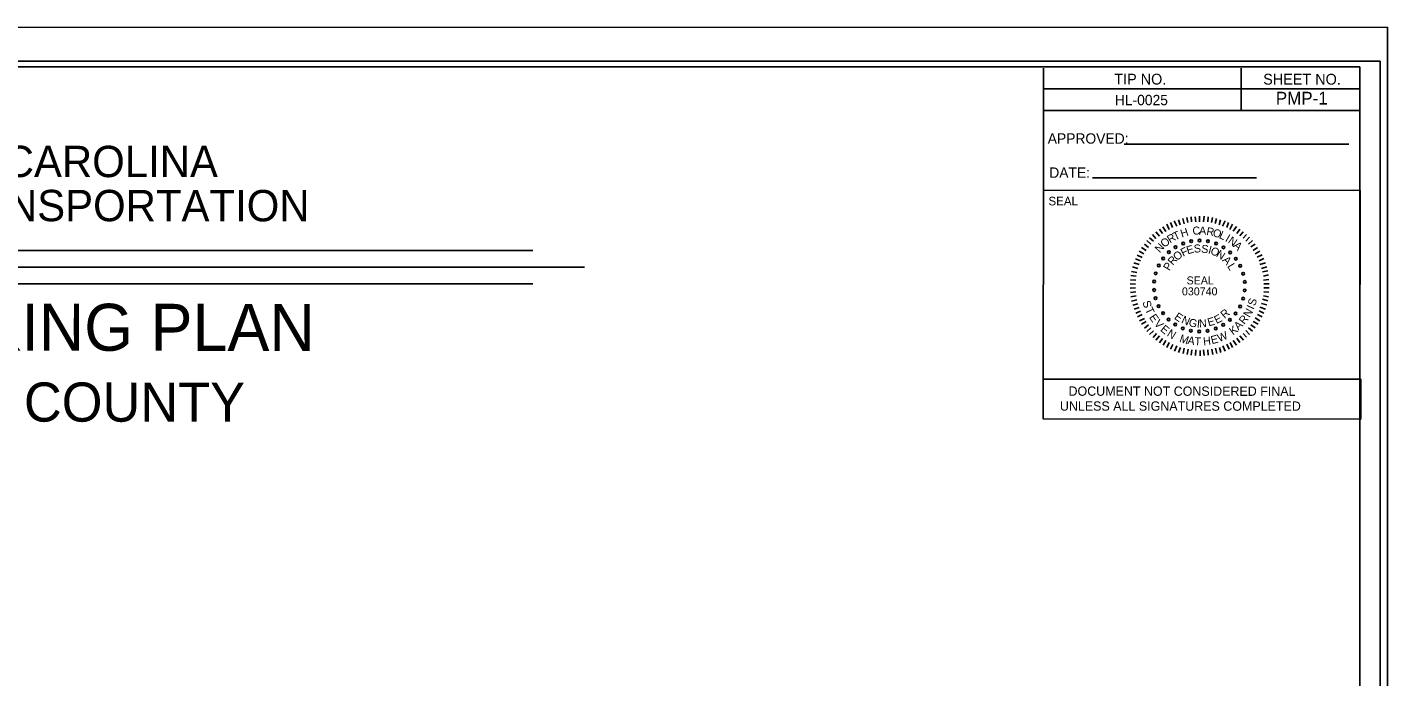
# Model space of a CAD drawing. Extents: x 2088685 to 2091711, y 751320 to 752417.
# Drawn here: x 2090071 to 2090874, y 752034 to 752417 of the extents above; entities that cross this region are included whole.
import ezdxf

# ---------------------------------------------------------------- set-up
doc = ezdxf.new("R2010")
doc.units = 0
for name, color, linetype in [('Default', 7, 'Continuous'), ('Matchline Text', 7, 'Continuous'), ('Old_Level_9', 7, 'Continuous'), ('Sheet Block Title CELL', 7, 'Continuous'), ('Sheet Data Field CELL', 7, 'Continuous'), ('Sheet Plan CELL', 7, 'Continuous'), ('Sheet Plot Border Inside CELL', 7, 'Continuous'), ('Sheet Plot Border Outside CELL', 7, 'Continuous'), ('Sheet Sticker Exception Certification CELL', 7, 'Continuous'), ('Sheet Title CELL', 7, 'Continuous')]:
    doc.layers.add(name, color=color, linetype=linetype)

msp = doc.modelspace()

# ---------------------------------------------------------------- linework, layer by layer
at = {"layer": 'Default'}
msp.add_line((2090718.89, 752347.92), (2090851.47, 752347.86), dxfattribs=at)
at = {"layer": 'Matchline Text'}
for p, q in [((2090787.95, 752367.8), (2090787.96, 752392.75)), ((2090858.18, 752392.71), (2090858.18, 752392.71)), ((2090858.18, 752392.71), (2090858.18, 752392.71)), ((2090858.18, 752392.71), (2090858.18, 752392.71)), ((2090858.18, 752392.71), (2090858.18, 752392.71)), ((2090858.18, 752392.71), (2090858.18, 752392.71)), ((2090858.18, 752392.71), (2090858.18, 752392.71)), ((2090858.18, 752392.71), (2090858.18, 752392.71)), ((2090858.18, 752392.71), (2090858.18, 752392.71)), ((2090700.2, 752328.03), (2090796.96, 752327.98))]:
    msp.add_line(p, q, dxfattribs=at)
at = {"layer": 'Old_Level_9'}
for p, q in [((2090748.44, 752302.61), (2090749.94, 752299.61)), ((2090751.06, 752303.36), (2090751.94, 752300.36)), ((2090753.44, 752304.11), (2090754.31, 752300.99)), ((2090755.81, 752304.61), (2090756.44, 752301.61)), ((2090758.44, 752304.99), (2090758.69, 752301.99)), ((2090760.81, 752305.11), (2090761.19, 752302.11)), ((2090763.44, 752305.36), (2090763.44, 752302.11)), ((2090766.06, 752305.36), (2090765.69, 752302.11)), ((2090768.44, 752304.99), (2090768.19, 752301.99)), ((2090771.06, 752304.61), (2090770.44, 752301.61)), ((2090773.44, 752304.11), (2090772.56, 752301.11)), ((2090775.81, 752303.36), (2090774.94, 752300.36)), ((2090778.44, 752302.61), (2090776.94, 752299.61)), ((2090735.69, 752294.61), (2090737.69, 752292.24)), ((2090737.69, 752296.24), (2090739.69, 752293.61)), ((2090739.69, 752297.74), (2090741.56, 752295.24)), ((2090741.69, 752299.11), (2090743.56, 752296.36)), ((2090744.06, 752300.61), (2090745.56, 752297.61)), ((2090746.31, 752301.61), (2090747.44, 752298.74)), ((2090780.56, 752301.61), (2090779.44, 752298.74)), ((2090782.81, 752300.61), (2090781.31, 752297.61)), ((2090785.19, 752299.36), (2090783.31, 752296.61)), ((2090787.19, 752297.74), (2090785.31, 752295.24)), ((2090789.19, 752296.24), (2090787.19, 752293.74)), ((2090791.19, 752294.61), (2090789.19, 752292.36)), ((2090729.19, 752286.86), (2090731.94, 752285.24)), ((2090730.81, 752288.99), (2090733.19, 752286.99)), ((2090732.19, 752290.99), (2090734.56, 752288.86)), ((2090733.94, 752292.74), (2090736.19, 752290.61)), ((2090792.94, 752292.99), (2090790.69, 752290.61)), ((2090794.69, 752290.99), (2090792.31, 752288.99)), ((2090796.31, 752288.99), (2090793.69, 752287.24)), ((2090797.69, 752286.99), (2090795.06, 752285.24)), ((2090725.56, 752280.24), (2090728.56, 752278.99)), ((2090726.56, 752282.49), (2090729.56, 752280.99)), ((2090727.81, 752284.86), (2090730.56, 752283.24)), ((2090799.06, 752284.86), (2090796.31, 752283.24)), ((2090800.31, 752282.61), (2090797.31, 752281.24)), ((2090801.31, 752280.49), (2090798.56, 752278.99)), ((2090722.81, 752270.49), (2090725.94, 752270.11)), ((2090723.19, 752272.86), (2090726.31, 752272.24)), ((2090723.81, 752275.49), (2090726.94, 752274.61)), ((2090724.56, 752277.86), (2090727.81, 752276.86)), ((2090802.31, 752277.86), (2090799.06, 752276.86)), ((2090803.06, 752275.49), (2090799.94, 752274.61)), ((2090803.69, 752273.11), (2090800.56, 752272.49)), ((2090804.06, 752270.74), (2090801.06, 752270.11)), ((2090722.44, 752265.49), (2090725.56, 752265.24)), ((2090722.44, 752262.86), (2090725.56, 752263.11)), ((2090722.56, 752267.86), (2090725.81, 752267.74)), ((2090804.31, 752268.11), (2090801.06, 752267.74)), ((2090804.44, 752265.49), (2090801.31, 752265.49)), ((2090804.44, 752263.11), (2090801.31, 752263.11)), ((2090722.56, 752260.36), (2090725.81, 752260.74)), ((2090722.81, 752257.86), (2090725.94, 752258.36)), ((2090723.19, 752255.36), (2090726.31, 752256.11)), ((2090803.69, 752255.49), (2090800.56, 752256.36)), ((2090804.06, 752257.86), (2090801.06, 752258.49)), ((2090804.31, 752260.49), (2090801.31, 752260.74)), ((2090723.94, 752252.99), (2090726.94, 752253.74)), ((2090724.81, 752250.61), (2090727.81, 752251.49)), ((2090725.81, 752248.11), (2090728.56, 752249.36)), ((2090726.81, 752245.99), (2090729.56, 752247.36)), ((2090800.31, 752245.99), (2090797.56, 752247.36)), ((2090801.31, 752248.11), (2090798.56, 752249.61)), ((2090802.31, 752250.61), (2090799.06, 752251.74)), ((2090803.06, 752253.11), (2090799.94, 752253.99)), ((2090727.94, 752243.61), (2090730.81, 752245.11)), ((2090729.19, 752241.61), (2090731.94, 752243.24)), ((2090730.81, 752239.36), (2090733.31, 752241.36)), ((2090732.31, 752237.36), (2090734.69, 752239.61)), ((2090794.69, 752237.61), (2090792.31, 752239.61)), ((2090796.31, 752239.61), (2090793.69, 752241.36)), ((2090797.94, 752241.61), (2090795.06, 752243.36)), ((2090799.06, 752243.61), (2090796.31, 752245.36)), ((2090733.94, 752235.61), (2090736.31, 752237.74)), ((2090735.94, 752233.86), (2090737.94, 752236.24)), ((2090737.69, 752232.24), (2090739.69, 752234.86)), ((2090739.69, 752230.61), (2090741.56, 752233.24)), ((2090741.94, 752229.24), (2090743.56, 752231.99)), ((2090744.06, 752227.99), (2090745.56, 752230.86)), ((2090782.94, 752227.99), (2090781.56, 752230.86)), ((2090785.19, 752229.24), (2090783.31, 752231.99)), ((2090787.19, 752230.86), (2090785.31, 752233.36)), ((2090789.31, 752232.24), (2090787.19, 752234.86)), ((2090791.19, 752233.99), (2090789.19, 752236.24)), ((2090792.94, 752235.61), (2090790.69, 752237.99)), ((2090746.31, 752226.86), (2090747.69, 752229.61)), ((2090748.69, 752225.86), (2090749.94, 752228.86)), ((2090751.06, 752224.99), (2090752.06, 752227.99)), ((2090753.69, 752224.49), (2090754.31, 752227.49)), ((2090756.06, 752223.86), (2090756.69, 752226.99)), ((2090758.44, 752223.49), (2090758.81, 752226.49)), ((2090761.06, 752223.24), (2090761.19, 752226.49)), ((2090763.69, 752223.11), (2090763.69, 752226.24)), ((2090766.06, 752223.24), (2090765.81, 752226.49)), ((2090768.56, 752223.49), (2090768.19, 752226.49)), ((2090771.19, 752223.86), (2090770.56, 752226.99)), ((2090773.56, 752224.49), (2090772.81, 752227.49)), ((2090775.94, 752224.99), (2090775.19, 752227.99)), ((2090778.44, 752225.86), (2090777.19, 752228.99)), ((2090780.81, 752226.86), (2090779.44, 752229.86))]:
    msp.add_line(p, q, dxfattribs=at)
for centre in [(2090749.27, 752287.13), (2090753.72, 752289.32), (2090758.49, 752290.66), (2090763.43, 752291.1), (2090768.37, 752290.62), (2090773.13, 752289.24), (2090777.56, 752287.02), (2090741.95, 752280.51), (2090745.31, 752284.16), (2090781.5, 752284.02), (2090784.83, 752280.34), (2090737.52, 752271.69), (2090739.33, 752276.3), (2090787.42, 752276.11), (2090789.19, 752271.49), (2090736.57, 752261.86), (2090736.59, 752266.82), (2090790.06, 752261.65), (2090790.08, 752266.61), (2090737.46, 752256.99), (2090789.13, 752256.78), (2090739.24, 752252.36), (2090741.83, 752248.13), (2090784.7, 752247.97), (2090787.32, 752252.17), (2090745.15, 752244.46), (2090749.1, 752241.45), (2090753.53, 752239.23), (2090758.29, 752237.85), (2090763.22, 752237.38), (2090768.16, 752237.81), (2090772.93, 752239.15), (2090777.38, 752241.34), (2090781.35, 752244.32)]:
    msp.add_circle(centre, 0.788, dxfattribs=at)
at = {"layer": 'Sheet Block Title CELL'}
for p, q in [((2090671.22, 752367.86), (2090671.23, 752392.8)), ((2090787.95, 752367.8), (2090787.96, 752392.75)), ((2090671.23, 752380.59), (2090787.95, 752380.53)), ((2090787.95, 752380.53), (2090858.17, 752380.49)), ((2090671.2, 752320.69), (2090671.22, 752367.86)), ((2090671.22, 752367.86), (2090858.17, 752367.76))]:
    msp.add_line(p, q, dxfattribs=at)
for points in [[(2090858, 752393.6), (2089358.33, 752393.49), (2089358.41, 751343.72), (2090858.08, 751343.83)], [(2090671.2, 752320.69), (2090858.14, 752320.6), (2090858.09, 752209.23), (2090671.15, 752209.31)]]:
    msp.add_lwpolyline(points, close=True, dxfattribs=at)
at = {"layer": 'Sheet Plan CELL'}
for p, q in [((2090874.42, 752416.91), (2090874.42, 752416.91)), ((2090869.93, 752396.91), (2090869.93, 752396.91))]:
    msp.add_line(p, q, dxfattribs=at)
at = {"layer": 'Sheet Plot Border Inside CELL'}
msp.add_lwpolyline([(2090869.93, 752396.91), (2089204.86, 752396.79), (2089204.94, 751341.13), (2090870.01, 751341.25)], close=True, dxfattribs=at)
at = {"layer": 'Sheet Plot Border Outside CELL'}
msp.add_lwpolyline([(2090874.42, 752416.91), (2089191.88, 752416.79), (2089191.96, 751321.13), (2090874.5, 751321.25)], close=True, dxfattribs=at)
at = {"layer": 'Sheet Sticker Exception Certification CELL'}
msp.add_lwpolyline([(2090671.15, 752209.31), (2090858.55, 752209.23), (2090858.54, 752185.73), (2090671.14, 752185.82)], close=True, dxfattribs=at)
at = {"layer": 'Sheet Title CELL'}
for p, q in [((2089677.86, 752285.08), (2090369.97, 752285.08)), ((2089645.9, 752275.34), (2090400.31, 752275.34)), ((2089677.86, 752265.58), (2090369.97, 752265.58))]:
    msp.add_line(p, q, dxfattribs=at)

# ---------------------------------------------------------------- texts
at = {"layer": 'Default'}
for s, height, p in [('TIP NO.', 6.356, (2090713.08, 752383.12)), ('SHEET NO.', 6.356, (2090800.97, 752383.07)), ('HL-0025', 6.108, (2090713.41, 752370.9)), ('APPROVED:', 6.108, (2090673.8, 752348.21)), ('DATE:', 6.108, (2090674.71, 752328.07)), ('SEAL', 5.093, (2090674.22, 752311.78))]:
    msp.add_text(s, height=height, rotation=359.96835, dxfattribs=at).set_placement(p)
at = {"layer": 'Old_Level_9'}
for s, height, rotation, p in [('R', 4.72, 32.17545, (2090746.06, 752289.24)), ('T', 4.72, 25.43578, (2090749.06, 752290.99)), ('H', 4.72, 17.74335, (2090752.94, 752292.74)), ('C', 4.72, 4.93991, (2090759.44, 752294.36)), ('A', 4.72, 357.97486, (2090763.06, 752294.61)), ('R', 4.72, 350.02156, (2090767.19, 752294.36)), ('O', 4.72, 343.0868, (2090770.81, 752293.74)), ('L', 4.72, 335.7459, (2090774.56, 752292.61)), ('I', 4.72, 330.80596, (2090778.19, 752290.86)), ('N', 4.72, 48.06666, (2090739.94, 752283.49)), ('O', 4.72, 39.94421, (2090742.69, 752286.61)), ('F', 4.7, 26.39995, (2090753.69, 752281.49)), ('E', 4.7, 16.58893, (2090756.44, 752282.86)), ('S', 4.7, 4.46802, (2090760.19, 752283.86)), ('S', 4.7, 353.04145, (2090764.19, 752283.99)), ('I', 4.7, 345.48207, (2090768.19, 752283.49)), ('O', 4.7, 337.87488, (2090769.44, 752283.24)), ('N', 4.72, 324.90384, (2090779.81, 752289.99)), ('A', 4.72, 317.00507, (2090782.94, 752287.61)), ('R', 4.7, 49.7478, (2090747.69, 752276.11)), ('O', 4.7, 38.25181, (2090750.06, 752278.86)), ('N', 4.7, 327.39302, (2090772.81, 752281.86)), ('A', 4.7, 313.94377, (2090776.56, 752279.24)), ('P', 4.7, 60.12364, (2090745.69, 752272.86)), ('L', 4.7, 301.53231, (2090779.56, 752275.86)), ('S', 4.72, 288.212, (2090729.62, 752254.76)), ('S', 4.72, 72.25788, (2090796.16, 752252.12)), ('T', 4.72, 295.62438, (2090731.11, 752250.36)), ('E', 4.72, 303.82249, (2090733.45, 752245.76)), ('E', 4.7, 324.86919, (2090748.06, 752245.11)), ('N', 4.7, 336.05836, (2090752.31, 752242.61)), ('E', 4.7, 27.15681, (2090773.44, 752241.74)), ('R', 4.7, 40.34926, (2090778.19, 752244.74)), ('R', 4.72, 51.15031, (2090789.8, 752241.21)), ('N', 4.72, 59.37257, (2090792.87, 752245.26)), ('I', 4.72, 66.04639, (2090795.29, 752250.01)), ('V', 4.72, 311.92979, (2090736.27, 752241.79)), ('E', 4.72, 320.23124, (2090739.89, 752238.07)), ('N', 4.72, 328.32899, (2090743.8, 752235.04)), ('G', 4.7, 347.48124, (2090756.69, 752240.61)), ('I', 4.7, 355.62459, (2090761.69, 752239.74)), ('N', 4.7, 3.12779, (2090763.19, 752239.74)), ('E', 4.7, 15.80569, (2090768.81, 752240.36)), ('K', 4.72, 36.141, (2090783.06, 752235.04)), ('A', 4.72, 43.52169, (2090786.35, 752237.87)), ('M', 4.72, 342.33704, (2090751.19, 752231.29)), ('A', 4.72, 350.18217, (2090756.05, 752230)), ('T', 4.72, 357.38659, (2090760.31, 752229.3)), ('H', 4.72, 6.01122, (2090765.75, 752229.16)), ('E', 4.72, 14.16475, (2090770.67, 752229.89)), ('W', 4.72, 22.00576, (2090775, 752231.09))]:
    msp.add_text(s, height=height, rotation=rotation, dxfattribs=at).set_placement(p)
for s, p in [('030740', (2090753.01, 752258.7)), ('SEAL', (2090755.76, 752265.16))]:
    msp.add_text(s, height=4.699, dxfattribs=at).set_placement(p)
at = {"layer": 'Sheet Data Field CELL'}
for s, height, rotation, p in [('PMP-1', 7.5, 0.00423, (2090808.4, 752371.3)), ('STATE OF NORTH CAROLINA', 18.4936, 359.97341, (2089835.03, 752328.6)), ('DEPARTMENT OF TRANSPORTATION', 18.4936, 359.97341, (2089791.59, 752302.59)), ('PAVEMENT MARKING PLAN', 27.7403, 359.97341, (2089746.49, 752226.16)), ('MECKLENBURG COUNTY', 23.1165, 359.97341, (2089822.19, 752184.31))]:
    msp.add_text(s, height=height, rotation=rotation, dxfattribs=at).set_placement(p)
at = {"layer": 'Sheet Sticker Exception Certification CELL'}
for s, p in [('DOCUMENT NOT CONSIDERED FINAL', (2090686.06, 752199.46)), ('UNLESS ALL SIGNATURES COMPLETED', (2090680.99, 752190.66))]:
    msp.add_text(s, height=5.4983, rotation=359.97341, dxfattribs=at).set_placement(p)

doc.saveas('drawing.dxf')
